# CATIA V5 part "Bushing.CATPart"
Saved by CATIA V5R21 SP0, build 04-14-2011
Part number: Bushing
Bounding box of the stored display mesh (mm): x -13.45 to 13.45, y 0 to 63, z -13.45 to 13.45
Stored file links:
  D:\CATIA V5R21 E-RESOURCES\CATIA-V5R21\catia-v5r21-Prts\c14_catia_v5r21_prt\c14-catia-v5r21-figr-14-26 & 27\Part & Asm\Bushing.CATPart
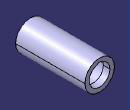
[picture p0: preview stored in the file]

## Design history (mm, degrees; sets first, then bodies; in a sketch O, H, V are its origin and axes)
Body1 (main body)
  Sketch1 on zx-plane, origin (0, 0, 0), H (-1, 0, 0), V (0, 0, 1)
    circle A1 centre (0, 0) radius 9.5
    circle A2 centre (0, 0) radius 13.45
    radius A1 = 9.5
    radius A2 = 13.45
  Pad1: profile Sketch1, direction (0, 1, 0), length 63
  Sketch2 on face of Pad1, origin (0, 63, 0), H (-1, 0, 0), V (0, 0, 1)
    line L1 (-1.5, 9.3808) -> (1.5, 9.3808)
    line L2 (1.5, 9.3808) -> (1.5, 10.1808)
    line L3 (1.5, 10.1808) -> (-1.5, 10.1808)
    line L4 (-1.5, 10.1808) -> (-1.5, 9.3808)
    point P2 (1.5, 9.3808)
    reference projected circle E1 centre (0, 0) radius 9.5 from edge of Pad1
    length L3 = 3
    length L2 = 0.8
    distance V L4 = 1.5
    horizontal: L1 H, L3 H
    vertical: L2 V, L4 V
    coincidence: P2 E1
  Pocket1: profile Sketch2, direction (0, -1, 0), through (limit type 6)
  Sketch3 on xy-plane, origin (0, 0, 0), H (1, 0, 0), V (0, 1, 0)
    line L1 (9.5, 57) -> (10.3, 57)
    line L2 (10.3, 57) -> (10.3, 49)
    line L3 (10.3, 49) -> (9.5, 49)
    line L4 (9.5, 49) -> (9.5, 57)
    reference projected line E1 (13.45, 63) -> (-13.45, 63) from edge of Pad1
    length L2 = 8
    length L1 = 0.8
    distance L3 E1 = 14
    distance V L4 = 9.5
    horizontal: L1 H, L3 H
    vertical: L2 V, L4 V
  Groove1: profile Sketch3, axis axis of face of Pad1, angle 360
